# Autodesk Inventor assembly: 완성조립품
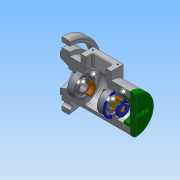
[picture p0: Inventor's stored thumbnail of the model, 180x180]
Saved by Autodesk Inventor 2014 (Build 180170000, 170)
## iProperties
Created: 2017-05
Part Number: 완성조립품
Document SubType Name: Assembly
Designer: Administrator
Author: Administrator
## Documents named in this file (12)
- C:\Users\Administrator\Desktop\470507V1004\완성조립품.iam
- C:\Users\Administrator\Desktop\470507V1004\본체.ipt
- C:\Users\Administrator\Desktop\470507V1004\축.ipt
- C:\Users\Administrator\Desktop\470507V1004\부시1.ipt
- C:\Users\Administrator\Desktop\470507V1004\베어링 15 x 35 x 11.ipt
- C:\Users\Administrator\Desktop\470507V1004\멈춤링 35x1.6.ipt
- C:\Users\Administrator\Desktop\470507V1004\부시2.ipt
- C:\Users\Administrator\Desktop\470507V1004\와셔 10x21.ipt
- C:\Users\Administrator\Desktop\470507V1004\너트 M10.ipt
- C:\Users\Administrator\Desktop\470507V1004\사이드 커버.ipt
- 사이드 커버.ipt
- C:\Users\Administrator\Desktop\470507V1004\멈춤링 15 x 1.ipt
